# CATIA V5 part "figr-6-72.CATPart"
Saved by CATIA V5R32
Part number: Part2
Bounding box of the stored display mesh (mm): x -37.886 to 37.886, y -61.415 to 61.415, z 0 to 29
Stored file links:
  D:\PROJECTS\Project 2022\CATIA V5 6R 2022\Resources\Part Files\c06_catia_v5_6r2022_prt\figr-6-72.CATPart
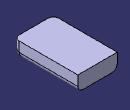
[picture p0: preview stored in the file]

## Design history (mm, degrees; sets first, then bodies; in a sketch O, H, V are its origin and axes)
Body1 (main body)
  Sketch1 on xy-plane, origin (0, 0, 0), H (1, 0, 0), V (0, 1, 0)
    line L1 (37.8862, 61.4155) -> (37.8862, -61.4155)
    line L2 (37.8862, -61.4155) -> (-37.8862, -61.4155)
    line L3 (-37.8862, -61.4155) -> (-37.8862, 61.4155)
    line L4 (-37.8862, 61.4155) -> (37.8862, 61.4155)
    vertical: L1 V, L3 V
    horizontal: L2 H, L4 H
    equidistance: L1 L3 O, L2 L4 O
  Pad1: profile Sketch1, direction (0, 0, 1), length 29
  Fillet1: radius 10, on edge [face of Pad1 | face of Pad1] (x5)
